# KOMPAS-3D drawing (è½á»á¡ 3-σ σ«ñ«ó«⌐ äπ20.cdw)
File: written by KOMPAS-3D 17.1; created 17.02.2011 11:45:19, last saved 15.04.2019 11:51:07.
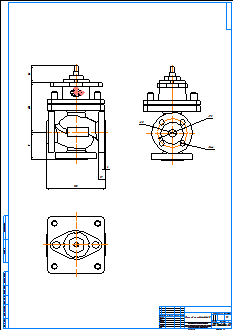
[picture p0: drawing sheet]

Title block, sheet 1: name: Клапан 3-х ходовой Ду20; material: Внимание! Данный продукт является объектом авторского права ООО «Торговый Дом АДЛ». / Запрещается изменение, копирование, распространение / (в том числе путем копирования на другие сайты и ресурсы в Интернете) / или любое иное использование информации и объектов без предварительного / согласия правообладателя (ООО «Торговый Дом АДЛ»).; scale: 1:1; sheets: 1; organisation: ООО "Торговый дом АДЛ"; sheet format: A1; stored path: \\adlc.lan\data\АДЛ_ПКД\3D-модели\ADL production\Клапаны ГРАНРЕГ\Трёхходовой клапан КМ307Ф\KOMPAS 2D\Клапан 3-х ходовой Ду20.cdw

Views: Спереди 1, Проекционный вид 2, Проекционный вид 3
Dimensions and other numbers on the sheet: 150; 70; 126; 43; 20; 75; 14; 3; 19; 1:1; 1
